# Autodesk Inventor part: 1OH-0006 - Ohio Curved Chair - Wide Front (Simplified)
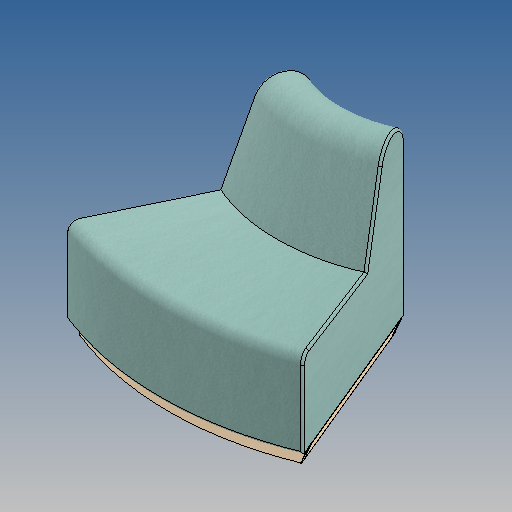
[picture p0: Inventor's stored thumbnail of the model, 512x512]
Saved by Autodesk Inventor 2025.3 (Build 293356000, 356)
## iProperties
Created: 2025-11
Part Number: 1OH-0006 - Ohio Curved Chair - Wide Front (Simplified)
Material: Generic
Document SubType Name: Modeling
Designer: craig.ferris
Density: 1 g/cm^3
Appearance: CADET-ZEST SEAFOAM (219)
Author: craig.ferris
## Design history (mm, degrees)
body "Solid1"
body "Solid2"
body "Solid3"
body "Solid4"
body "Solid5"
body "Solid6"
body "Solid7"
body "Solid8"
body "Solid9"
body "Solid10"
